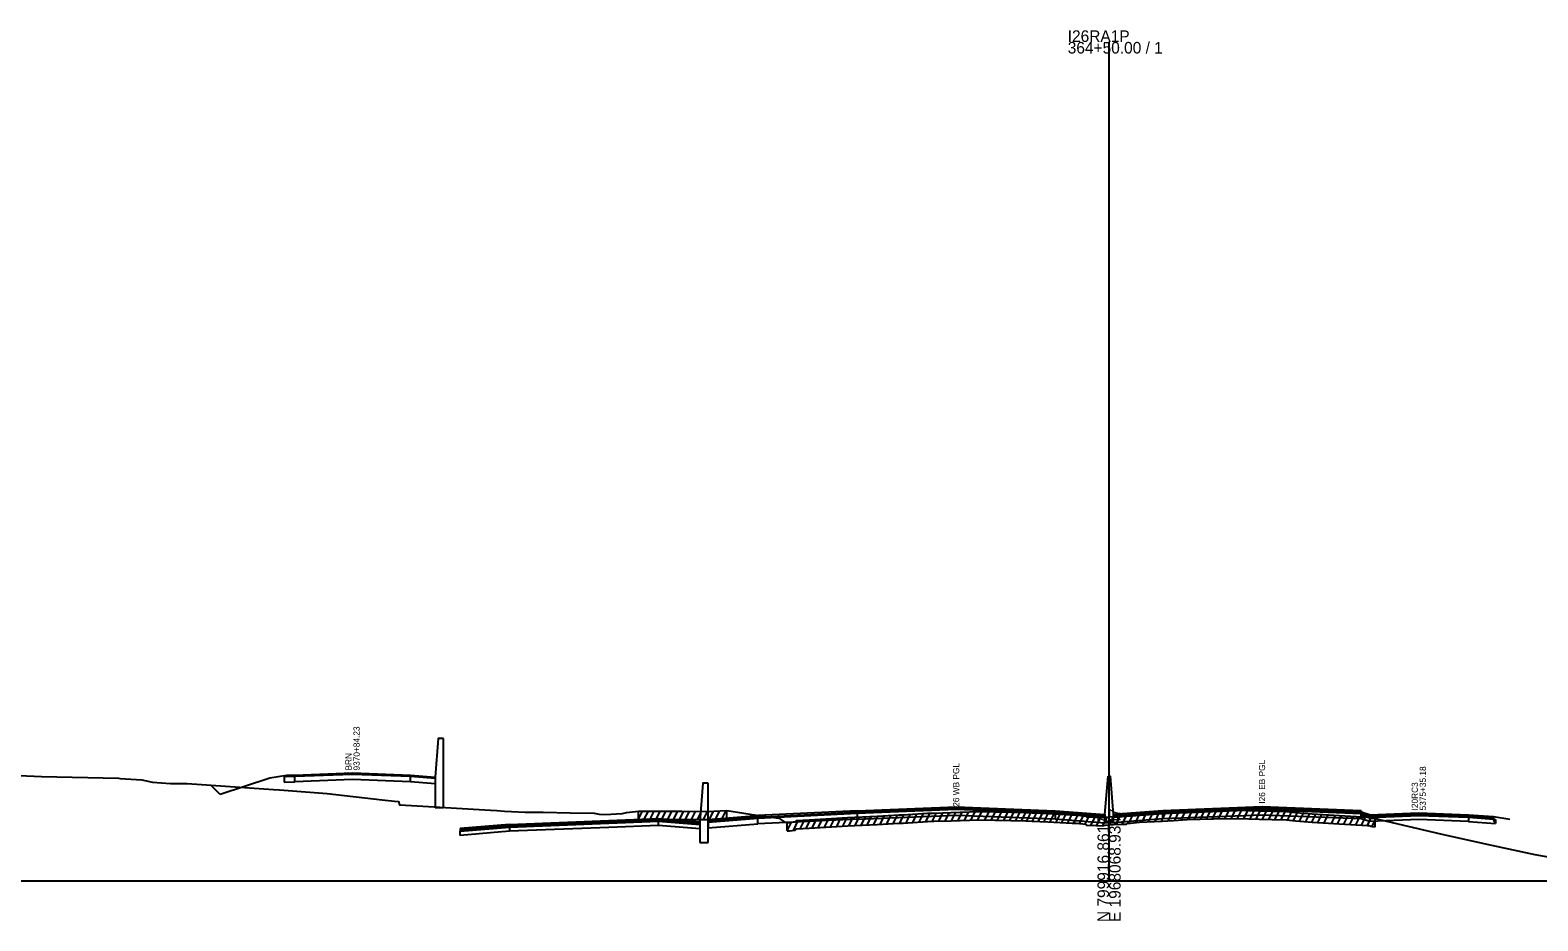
# Model space of a CAD drawing. Extents: x 1017 to 19997, y -1947 to 50737.
# Drawn here: x 14339 to 14703.7, y 14490.3 to 14705.6 of the extents above; entities that cross this region are included whole.
import ezdxf

# ---------------------------------------------------------------- set-up
doc = ezdxf.new("R2010")
doc.units = 0
for name, color, linetype in [('RD_GPK_XS_Cell', 7, 'Continuous'), ('RD_XS_Base', 7, 'Continuous'), ('RD_XS_ExGround', 7, 'Continuous'), ('RD_XS_ExPaveRet', 7, 'Continuous'), ('RD_XS_Greenside', 7, 'Continuous'), ('RD_XS_MedBWall', 7, 'Continuous'), ('RD_XS_Pave', 7, 'Continuous'), ('RD_XS_PaveOvlay', 7, 'Continuous'), ('RD_XS_TieSlope', 7, 'Continuous'), ('RD_XS_TX_Notes', 7, 'Continuous')]:
    doc.layers.add(name, color=color, linetype=linetype)

msp = doc.modelspace()

# ---------------------------------------------------------------- linework, layer by layer
at = {"layer": 'RD_GPK_XS_Cell'}
for p, q in [((14600, 14500), (14600, 14702.73)), ((14000, 14500), (14600, 14500)), ((14600, 14500), (15200, 14500))]:
    msp.add_line(p, q, dxfattribs=at)
at = {"layer": 'RD_XS_Base'}
for points in [[(14403, 14525.23), (14400.5, 14525.13)], [(14400.5, 14525.13), (14400.5, 14523.79)], [(14400.5, 14523.79), (14403, 14523.89)], [(14403, 14525.23), (14417, 14525.79), (14431, 14525.23)], [(14403, 14523.89), (14403, 14525.23)], [(14431, 14523.91), (14417, 14524.45), (14403, 14523.89)], [(14431, 14523.91), (14431, 14525.23)], [(14431, 14525.23), (14437, 14524.75)], [(14437, 14523.43), (14431, 14523.91)], [(14437, 14524.75), (14437, 14523.43)], [(14539.05, 14516.25), (14539.05, 14514.91)], [(14539.05, 14514.91), (14563, 14515.88), (14587, 14514.92)], [(14599, 14515.32), (14587, 14516.26)], [(14587, 14516.26), (14587, 14514.92)], [(14613, 14514.92), (14613, 14516.26)], [(14660.95, 14514.92), (14637, 14515.88), (14613, 14514.92)], [(14660.95, 14514.92), (14660.95, 14516.26)], [(14660.95, 14514.95), (14660.95, 14515.95)], [(14660.95, 14515.95), (14662.97, 14515.3)], [(14661, 14516.26), (14661, 14514.92)], [(14443, 14511.96), (14455, 14512.94)], [(14443, 14510.96), (14443, 14511.96)], [(14455, 14511.94), (14443, 14510.96)], [(14491, 14513.38), (14479, 14512.9), (14455, 14511.94)], [(14455, 14512.94), (14455, 14511.94)], [(14491, 14514.38), (14501, 14513.58)], [(14491, 14513.38), (14491, 14514.38)], [(14501, 14512.58), (14491, 14513.38)], [(14501, 14513.58), (14501, 14512.58)], [(14503, 14514.09), (14503, 14512.75)], [(14503, 14512.75), (14515, 14513.71)], [(14515, 14513.71), (14515, 14515.05)], [(14539.05, 14514.91), (14515, 14513.71)], [(14587, 14514.92), (14599, 14513.98)], [(14599, 14513.98), (14599, 14515.32)], [(14601, 14513.98), (14601, 14515.32)], [(14613, 14514.92), (14601, 14513.98)], [(14662.97, 14514.3), (14660.95, 14514.95)], [(14661, 14514.92), (14660.95, 14514.92)], [(14662.97, 14515.3), (14662.97, 14514.3)], [(14686.98, 14514.32), (14674.97, 14514.79), (14662.97, 14514.3)], [(14686.98, 14515.32), (14686.98, 14514.32)], [(14693.48, 14513.81), (14692.98, 14514.85), (14686.98, 14515.32)], [(14686.98, 14515.32), (14692.98, 14514.85), (14693.48, 14514.81)], [(14686.98, 14514.32), (14693.48, 14513.81)], [(14693.48, 14514.81), (14693.48, 14513.81)]]:
    msp.add_lwpolyline(points, dxfattribs=at)
at = {"layer": 'RD_XS_ExGround'}
msp.add_lwpolyline([(14336.33, 14525.42), (14341.74, 14525.22), (14360.39, 14524.77), (14360.78, 14524.74), (14365.99, 14524.37), (14368.59, 14523.84), (14372.94, 14523.49), (14373.44, 14523.46), (14376.96, 14523.46), (14397.91, 14522.07), (14399.36, 14521.97), (14410.83, 14521.06), (14424.13, 14519.53), (14427.12, 14519.22), (14428.12, 14519.13), (14428.32, 14518.33), (14431.23, 14518.16), (14450.39, 14517.05), (14451.94, 14516.94), (14453.78, 14516.83), (14458.73, 14516.56), (14459.47, 14516.54), (14460.56, 14516.55), (14461.85, 14516.57), (14463.1, 14516.6), (14469.63, 14516.37), (14475.44, 14516.3), (14476.69, 14516.12), (14478.06, 14515.97), (14482.27, 14516.23), (14483.24, 14516.51), (14486.14, 14516.85), (14490.43, 14516.83), (14496.65, 14516.78), (14502.81, 14516.76), (14507.55, 14516.96), (14515.76, 14515.72), (14520.09, 14515.14), (14521.31, 14514.35), (14522.13, 14514.02), (14522.66, 14514.07), (14524.1, 14514.21), (14524.41, 14514.53), (14527.44, 14514.71), (14532.89, 14515.04), (14536.73, 14515.24), (14543.94, 14515.61), (14549.22, 14515.9), (14550.2, 14515.95), (14551.33, 14516.02), (14556.09, 14516.3), (14557.64, 14516.36), (14561.79, 14516.48), (14568.38, 14516.75), (14572.37, 14516.64), (14573.21, 14516.62), (14576.27, 14516.55), (14579.87, 14516.47), (14581.42, 14516.4), (14585.22, 14516.25), (14591.05, 14515.94), (14592.06, 14515.89), (14593.64, 14515.72), (14594.25, 14515.66), (14594.56, 14515.46), (14596.98, 14515.37), (14598.42, 14515.3), (14599.15, 14515.4), (14600, 14515.47), (14601.09, 14515.56), (14603.19, 14515.66), (14604.22, 14515.7), (14604.46, 14515.89), (14605.16, 14515.95), (14607.35, 14516.15), (14610.96, 14516.32), (14612.86, 14516.4), (14615.56, 14516.57), (14618.9, 14516.79), (14625.24, 14516.93), (14630.82, 14517.05), (14631.27, 14517.04), (14636.33, 14516.87), (14639.48, 14516.78), (14642.94, 14516.69), (14645.06, 14516.51), (14649.11, 14516.16), (14655.66, 14515.74), (14662.52, 14515.37), (14662.9, 14515.35), (14663.33, 14515.17), (14663.63, 14515.13), (14664.38, 14515.05), (14680.21, 14511.36), (14691.41, 14508.86), (14702.99, 14506.37), (14716.51, 14503.89)], dxfattribs=at)
at = {"layer": 'RD_XS_ExPaveRet'}
for p, q in [((14486.14, 14514.85), (14487.14, 14516.85)), ((14486.14, 14514.85), (14486.14, 14516.85)), ((14487.56, 14514.85), (14488.56, 14516.84)), ((14488.98, 14514.84), (14489.98, 14516.84)), ((14490.41, 14514.83), (14491.4, 14516.83)), ((14491.82, 14514.82), (14492.82, 14516.81)), ((14493.24, 14514.81), (14494.24, 14516.8)), ((14494.67, 14514.8), (14495.66, 14516.79)), ((14496.1, 14514.79), (14497.1, 14516.78)), ((14497.54, 14514.78), (14498.54, 14516.78)), ((14498.98, 14514.77), (14499.98, 14516.77)), ((14500.42, 14514.77), (14501.42, 14516.76)), ((14501.86, 14514.76), (14502.86, 14516.76)), ((14503.31, 14514.78), (14504.33, 14516.82)), ((14504.79, 14514.84), (14505.81, 14516.89)), ((14506.34, 14514.91), (14507.36, 14516.95)), ((14507.55, 14514.96), (14507.55, 14516.96)), ((14538.55, 14513.34), (14539.58, 14515.39)), ((14540.04, 14513.41), (14541.06, 14515.46)), ((14541.52, 14513.48), (14542.54, 14515.54)), ((14543.07, 14513.56), (14544.1, 14515.61)), ((14544.64, 14513.64), (14545.67, 14515.7)), ((14546.21, 14513.73), (14547.24, 14515.79)), ((14547.79, 14513.82), (14548.81, 14515.87)), ((14549.36, 14513.9), (14550.39, 14515.96)), ((14550.93, 14514), (14551.96, 14516.06)), ((14552.51, 14514.09), (14553.54, 14516.15)), ((14554.08, 14514.18), (14555.11, 14516.25)), ((14555.67, 14514.28), (14556.69, 14516.32)), ((14557.23, 14514.34), (14558.25, 14516.38)), ((14558.79, 14514.39), (14559.81, 14516.42)), ((14560.35, 14514.44), (14561.37, 14516.47)), ((14561.91, 14514.49), (14562.93, 14516.53)), ((14563.48, 14514.55), (14564.5, 14516.59)), ((14565.04, 14514.61), (14566.07, 14516.65)), ((14566.61, 14514.68), (14567.63, 14516.72)), ((14568.24, 14514.74), (14569.23, 14516.72)), ((14569.99, 14514.7), (14570.98, 14516.68)), ((14571.51, 14514.66), (14572.5, 14516.64)), ((14573.03, 14514.62), (14574.02, 14516.6)), ((14574.51, 14514.59), (14575.5, 14516.56)), ((14575.98, 14514.55), (14576.97, 14516.53)), ((14577.41, 14514.52), (14578.4, 14516.5)), ((14578.84, 14514.49), (14579.83, 14516.47)), ((14580.08, 14514.46), (14581.07, 14516.42)), ((14581.47, 14514.4), (14582.45, 14516.36)), ((14582.9, 14514.35), (14583.88, 14516.31)), ((14584.33, 14514.29), (14585.31, 14516.25)), ((14585.76, 14514.22), (14586.73, 14516.17)), ((14587.18, 14514.15), (14588.15, 14516.1)), ((14588.6, 14514.07), (14589.58, 14516.02)), ((14590.02, 14514), (14591, 14515.94)), ((14591.44, 14513.92), (14592.41, 14515.85)), ((14592.84, 14513.81), (14593.79, 14515.71)), ((14594.25, 14513.66), (14595.14, 14515.44)), ((14595.62, 14513.42), (14596.6, 14515.38)), ((14598.53, 14513.31), (14599.59, 14515.43)), ((14600.1, 14513.48), (14601.14, 14515.56)), ((14601.64, 14513.59), (14602.66, 14515.64)), ((14603.16, 14513.66), (14604.18, 14515.7)), ((14604.77, 14513.91), (14605.82, 14516.01)), ((14606.38, 14514.06), (14607.43, 14516.16)), ((14607.98, 14514.18), (14609, 14516.23)), ((14609.55, 14514.26), (14610.58, 14516.3)), ((14611.13, 14514.33), (14612.15, 14516.37)), ((14612.7, 14514.39), (14613.73, 14516.45)), ((14614.29, 14514.49), (14615.32, 14516.55)), ((14615.88, 14514.59), (14616.91, 14516.66)), ((14617.47, 14514.69), (14618.5, 14516.76)), ((14619.06, 14514.79), (14620.08, 14516.82)), ((14620.64, 14514.83), (14621.65, 14516.85)), ((14622.09, 14514.86), (14623.11, 14516.88)), ((14623.55, 14514.89), (14624.56, 14516.91)), ((14625.01, 14514.92), (14626.02, 14516.94)), ((14626.47, 14514.95), (14627.48, 14516.98)), ((14628.01, 14514.99), (14629.02, 14517.01)), ((14629.55, 14515.02), (14630.56, 14517.04)), ((14631.09, 14515.04), (14632.07, 14517.01)), ((14632.59, 14514.99), (14633.58, 14516.96)), ((14634.1, 14514.94), (14635.08, 14516.91)), ((14635.6, 14514.89), (14636.58, 14516.86)), ((14637.11, 14514.85), (14638.09, 14516.82)), ((14638.62, 14514.81), (14639.6, 14516.78)), ((14640.13, 14514.76), (14641.12, 14516.74)), ((14641.64, 14514.72), (14642.63, 14516.69)), ((14643.15, 14514.67), (14644.11, 14516.59)), ((14644.63, 14514.55), (14645.59, 14516.47)), ((14646.1, 14514.42), (14647.06, 14516.34)), ((14647.57, 14514.29), (14648.53, 14516.21)), ((14649.04, 14514.16), (14650.01, 14516.1)), ((14650.53, 14514.07), (14651.49, 14516)), ((14652.07, 14513.97), (14653.04, 14515.9)), ((14653.79, 14513.86), (14654.76, 14515.79)), ((14655.28, 14513.76), (14656.25, 14515.7)), ((14656.78, 14513.68), (14657.75, 14515.62)), ((14658.23, 14513.6), (14659.21, 14515.55)), ((14659.68, 14513.52), (14660.66, 14515.47)), ((14661.1, 14513.45), (14662.07, 14515.39)), ((14522.13, 14512.02), (14523.18, 14514.12)), ((14522.13, 14512.02), (14522.13, 14514.02)), ((14523.63, 14512.16), (14524.82, 14514.55)), ((14525.26, 14512.58), (14526.29, 14514.64)), ((14526.73, 14512.67), (14527.76, 14514.73)), ((14528.2, 14512.76), (14529.23, 14514.82)), ((14529.67, 14512.85), (14530.7, 14514.91)), ((14531.15, 14512.94), (14532.18, 14515)), ((14532.63, 14513.03), (14533.66, 14515.08)), ((14534.12, 14513.11), (14535.14, 14515.16)), ((14535.6, 14513.19), (14536.62, 14515.24)), ((14537.08, 14513.26), (14538.1, 14515.31)), ((14597.07, 14513.37), (14598.05, 14515.32)), ((14662.5, 14513.37), (14663.4, 14515.16)), ((14663.64, 14513.13), (14664.38, 14514.61)), ((14664.38, 14513.05), (14664.38, 14515.05))]:
    msp.add_line(p, q, dxfattribs=at)
for points in [[(14486.14, 14514.85), (14490.43, 14514.83), (14496.65, 14514.78), (14502.81, 14514.76), (14507.55, 14514.96)], [(14522.13, 14512.02), (14522.66, 14512.07), (14524.1, 14512.21), (14524.41, 14512.53), (14527.44, 14512.71), (14532.89, 14513.04), (14536.73, 14513.24), (14543.94, 14513.61), (14549.22, 14513.9), (14550.2, 14513.95), (14551.33, 14514.02), (14556.09, 14514.3), (14557.64, 14514.36), (14561.79, 14514.48), (14568.38, 14514.75), (14572.37, 14514.64), (14573.21, 14514.62), (14576.27, 14514.55), (14579.87, 14514.47), (14581.42, 14514.4), (14585.22, 14514.25), (14591.05, 14513.94), (14592.06, 14513.89), (14593.64, 14513.72), (14594.25, 14513.66), (14594.56, 14513.46), (14596.98, 14513.37), (14598.42, 14513.3), (14599.15, 14513.4), (14600, 14513.47), (14601.09, 14513.56), (14603.19, 14513.66), (14604.22, 14513.7), (14604.46, 14513.89), (14605.16, 14513.95), (14607.35, 14514.15), (14610.96, 14514.32), (14612.86, 14514.4), (14615.56, 14514.57), (14618.9, 14514.79), (14625.24, 14514.93), (14630.82, 14515.05), (14631.27, 14515.04), (14636.33, 14514.87), (14639.48, 14514.78), (14642.94, 14514.69), (14645.06, 14514.51), (14649.11, 14514.16), (14655.66, 14513.74), (14662.52, 14513.37), (14662.9, 14513.35), (14663.33, 14513.17), (14663.63, 14513.13), (14664.38, 14513.05)]]:
    msp.add_lwpolyline(points, dxfattribs=at)
at = {"layer": 'RD_XS_Greenside'}
for points in [[(14397, 14524.82), (14385, 14520.82)], [(14401, 14525.46), (14397, 14524.82)], [(14692.98, 14515.49), (14696.98, 14514.85)]]:
    msp.add_lwpolyline(points, dxfattribs=at)
at = {"layer": 'RD_XS_MedBWall'}
for points in [[(14439, 14534.4), (14437.75, 14534.4), (14437, 14525.06)], [(14439, 14517.71), (14439, 14534.4)], [(14437, 14525.06), (14437, 14517.71)], [(14503, 14523.55), (14501.75, 14523.55), (14501, 14514.21)], [(14503, 14509.25), (14503, 14523.55)], [(14599, 14515.97), (14599.75, 14525.31)], [(14599.75, 14525.31), (14600.25, 14525.31), (14601, 14515.97)], [(14437, 14517.71), (14439, 14517.71)], [(14599, 14513.97), (14599, 14515.32), (14599, 14515.97)], [(14601, 14515.97), (14601, 14515.32), (14601, 14513.97)], [(14501, 14514.21), (14501, 14509.25)], [(14601, 14513.97), (14599, 14513.97)], [(14501, 14509.25), (14503, 14509.25)]]:
    msp.add_lwpolyline(points, dxfattribs=at)
at = {"layer": 'RD_XS_Pave'}
for points in [[(14503, 14514.43), (14515, 14515.39)], [(14515, 14515.39), (14539.05, 14516.59)], [(14539.05, 14516.25), (14515, 14515.05)], [(14515, 14515.05), (14515, 14515.39)], [(14587, 14516.26), (14563, 14517.22), (14539.05, 14516.25)], [(14539.05, 14516.59), (14539.05, 14516.25)], [(14587, 14516.6), (14587, 14516.26)], [(14587, 14516.6), (14599, 14515.66)], [(14599, 14515.66), (14599, 14515.32)], [(14613, 14516.6), (14601, 14515.66)], [(14601, 14515.32), (14613, 14516.26)], [(14601, 14515.66), (14601, 14515.32)], [(14660.95, 14516.6), (14637, 14517.56), (14613, 14516.6)], [(14613, 14516.26), (14637, 14517.22), (14660.95, 14516.26)], [(14613, 14516.26), (14613, 14516.6)], [(14660.95, 14516.6), (14661, 14516.6)], [(14660.95, 14516.26), (14660.95, 14516.6)], [(14662.97, 14515.62), (14660.95, 14516.28)], [(14660.95, 14516.28), (14660.95, 14515.95)], [(14661, 14516.26), (14660.95, 14516.26)], [(14661, 14516.6), (14661, 14516.26)], [(14686.98, 14515.64), (14674.97, 14516.11), (14662.97, 14515.62)], [(14662.97, 14515.3), (14674.97, 14515.79), (14686.98, 14515.32)], [(14662.97, 14515.62), (14662.97, 14515.3)], [(14686.98, 14515.32), (14686.98, 14515.64)], [(14686.98, 14515.64), (14692.98, 14515.17)], [(14455, 14513.26), (14443, 14512.29)], [(14443, 14512.29), (14443, 14511.96)], [(14491, 14514.7), (14479, 14514.22), (14455, 14513.26)], [(14455, 14512.94), (14479, 14513.9), (14491, 14514.38)], [(14455, 14513.26), (14455, 14512.94)], [(14491, 14514.38), (14491, 14514.7)], [(14491, 14514.7), (14501, 14513.9)], [(14501, 14513.9), (14501, 14513.58)], [(14515, 14515.05), (14503, 14514.09)], [(14503, 14514.09), (14503, 14514.43)], [(14692.98, 14514.85), (14686.98, 14515.32)], [(14692.98, 14515.17), (14692.98, 14514.85)]]:
    msp.add_lwpolyline(points, dxfattribs=at)
at = {"layer": 'RD_XS_PaveOvlay'}
for points in [[(14403, 14525.54), (14401, 14525.46)], [(14401, 14525.46), (14401, 14525.15)], [(14401, 14525.15), (14403, 14525.23)], [(14403, 14525.54), (14417, 14526.1), (14431, 14525.54)], [(14403, 14525.23), (14403, 14525.54)], [(14431, 14525.54), (14431, 14525.23)], [(14431, 14525.54), (14437, 14525.06)], [(14437, 14525.06), (14437, 14524.75)], [(14503, 14514.77), (14515, 14515.73)], [(14539.05, 14516.93), (14515, 14515.73)], [(14515, 14515.73), (14515, 14515.39)], [(14539.05, 14516.93), (14563, 14517.89), (14587, 14516.93)], [(14587, 14516.6), (14563, 14517.56), (14539.05, 14516.59)], [(14539.05, 14516.59), (14539.05, 14516.93)], [(14587, 14516.93), (14587, 14516.6)], [(14587, 14516.93), (14599, 14515.97)], [(14599, 14515.97), (14599, 14515.66)], [(14613, 14516.93), (14601, 14515.97)], [(14601, 14515.97), (14601, 14515.66)], [(14660.95, 14516.93), (14637, 14517.89), (14613, 14516.93)], [(14613, 14516.6), (14613, 14516.93)], [(14660.95, 14516.93), (14661, 14516.93)], [(14660.95, 14516.6), (14660.95, 14516.93)], [(14662.97, 14515.93), (14660.95, 14516.6)], [(14660.95, 14516.6), (14660.95, 14516.28)], [(14661, 14516.93), (14661, 14516.6)], [(14662.97, 14515.93), (14674.97, 14516.43), (14686.98, 14515.96)], [(14662.97, 14515.62), (14662.97, 14515.93)], [(14686.98, 14515.96), (14686.98, 14515.64)], [(14686.98, 14515.96), (14692.98, 14515.49)], [(14692.98, 14515.49), (14692.98, 14515.17)], [(14455, 14513.57), (14443, 14512.61)], [(14443, 14512.61), (14443, 14512.29)], [(14455, 14513.57), (14479, 14514.53), (14491, 14515.01)], [(14455, 14513.26), (14455, 14513.57)], [(14491, 14515.01), (14491, 14514.7)], [(14491, 14515.01), (14501, 14514.21)], [(14501, 14514.21), (14501, 14513.9)], [(14503, 14514.43), (14503, 14514.77)]]:
    msp.add_lwpolyline(points, dxfattribs=at)
at = {"layer": 'RD_XS_TieSlope'}
msp.add_lwpolyline([(14385, 14520.82), (14382.88, 14522.94)], dxfattribs=at)

# ---------------------------------------------------------------- texts
at = {"layer": 'RD_GPK_XS_Cell'}
for s, p in [('I26RA1P', (14590, 14702.73)), ('364+50.00 / 1', (14590, 14699.93))]:
    msp.add_text(s, height=2.8, dxfattribs=at).set_placement(p)
for s, p in [('N 799916.8617', (14600, 14490)), ('E 1968068.9347', (14602.8, 14490))]:
    msp.add_text(s, height=2.8, rotation=90, dxfattribs=at).set_placement(p)
at = {"layer": 'RD_XS_TX_Notes'}
for s, p in [(' 9370+84.23', (14418.73, 14526.08)), (' BRN', (14416.77, 14526.08)), ('I26 WB PGL', (14563.75, 14517.31)), ('I26 EB PGL', (14637.75, 14518.62)), (' 5375+35.18', (14676.65, 14516.43)), (' I20RC3', (14674.7, 14516.43))]:
    msp.add_text(s, height=1.5, rotation=90, dxfattribs=at).set_placement(p)

doc.saveas('drawing.dxf')
